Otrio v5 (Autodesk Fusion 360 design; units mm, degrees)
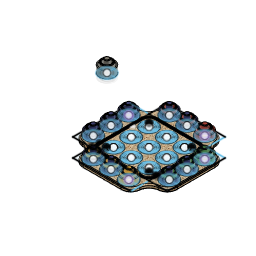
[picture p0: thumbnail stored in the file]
parameter "d19" = 32
parameter "d131" = 37
sketch "Esquisse1" plane through (0, 0, 0) normal (0, 1, 0) x axis (1, 0, 0)
  line L1 (-200.4818, 104.9767) -> (-200.4818, 114.9923)
  line L2 (-199.4818, 104.9731) -> (-199.4818, 114.991)
  circle C1 centre (-200, 100) radius 5
  circle C2 centre (-200, 100) radius 8
  circle C3 centre (-200, 100) radius 11
  circle C4 centre (-200, 100) radius 13
  circle C5 centre (-200, 100) radius 15
  circle C6 centre (-66, 89) radius 11
  circle C7 centre (-66, 89) radius 13
  circle C8 centre (-66, 89) radius 8
  circle C9 centre (-66, 89) radius 15
  circle C10 centre (-66, 89) radius 5
  circle C11 centre (-31, 89) radius 13
  circle C12 centre (-31, 89) radius 8
  circle C13 centre (-31, 89) radius 11
  circle C14 centre (-31, 89) radius 15
  circle C15 centre (-31, 89) radius 5
  circle C16 centre (4, 89) radius 11
  circle C17 centre (4, 89) radius 15
  circle C18 centre (4, 89) radius 13
  circle C19 centre (4, 89) radius 8
  circle C20 centre (4, 89) radius 5
  circle C21 centre (-31, 49) radius 11
  circle C22 centre (-31, 49) radius 5
  circle C23 centre (-31, 49) radius 8
  circle C24 centre (-66, 49) radius 15
  circle C25 centre (4, 49) radius 5
  circle C26 centre (4, 49) radius 13
  circle C27 centre (-31, 49) radius 13
  circle C28 centre (-66, 49) radius 5
  circle C29 centre (4, 49) radius 11
  circle C30 centre (4, 49) radius 15
  circle C31 centre (4, 49) radius 8
  circle C32 centre (-66, 49) radius 11
  circle C33 centre (-31, 49) radius 15
  circle C34 centre (-66, 49) radius 13
  circle C35 centre (-66, 49) radius 8
  circle C36 centre (4, 14) radius 5
  circle C37 centre (4, 14) radius 13
  circle C38 centre (4, 14) radius 8
  circle C39 centre (-31, 14) radius 8
  circle C40 centre (-31, 14) radius 15
  circle C41 centre (-31, 14) radius 11
  circle C42 centre (4, 14) radius 11
  circle C43 centre (-31, 14) radius 13
  circle C44 centre (4, 14) radius 15
  circle C45 centre (-66, 14) radius 15
  circle C46 centre (-31, 14) radius 5
  circle C47 centre (-66, 14) radius 11
  circle C48 centre (-66, 14) radius 5
  circle C49 centre (-66, 14) radius 13
  circle C50 centre (-66, 14) radius 8
  circle C51 centre (-31, -21) radius 15
  circle C52 centre (-31, -21) radius 8
  circle C53 centre (-31, -21) radius 5
  circle C54 centre (4, -21) radius 11
  circle C55 centre (4, -21) radius 8
  circle C56 centre (-66, -21) radius 11
  circle C57 centre (-66, -21) radius 5
  circle C58 centre (-66, -21) radius 13
  circle C59 centre (4, -21) radius 13
  circle C60 centre (-31, -21) radius 13
  circle C61 centre (4, -21) radius 5
  circle C62 centre (-31, -21) radius 11
  circle C63 centre (4, -21) radius 15
  circle C64 centre (-66, -21) radius 8
  circle C65 centre (-66, -21) radius 15
  circle C66 centre (-66, -61) radius 15
  circle C67 centre (-31, -61) radius 5
  circle C68 centre (4, -61) radius 13
  circle C69 centre (-31, -61) radius 15
  circle C70 centre (4, -61) radius 5
  circle C71 centre (4, -61) radius 11
  circle C72 centre (-31, -61) radius 13
  circle C73 centre (-31, -61) radius 11
  circle C74 centre (-31, -61) radius 8
  circle C75 centre (4, -61) radius 15
  circle C76 centre (4, -61) radius 8
  circle C77 centre (-66, -61) radius 13
  circle C78 centre (-66, -61) radius 11
  circle C79 centre (-66, -61) radius 8
  circle C80 centre (-66, -61) radius 5
  circle C81 centre (44, 49) radius 15
  circle C82 centre (44, 49) radius 13
  circle C83 centre (44, 49) radius 11
  circle C84 centre (44, 49) radius 8
  circle C85 centre (44, 49) radius 5
  circle C86 centre (44, 14) radius 15
  circle C87 centre (44, 14) radius 5
  circle C88 centre (44, 14) radius 8
  circle C89 centre (44, 14) radius 13
  circle C90 centre (44, 14) radius 11
  circle C91 centre (44, -21) radius 5
  circle C92 centre (44, -21) radius 11
  circle C93 centre (44, -21) radius 15
  circle C94 centre (44, -21) radius 8
  circle C95 centre (44, -21) radius 13
  circle C96 centre (-106, 49) radius 15
  circle C97 centre (-106, 49) radius 13
  circle C98 centre (-106, 49) radius 11
  circle C99 centre (-106, 49) radius 8
  circle C100 centre (-106, 49) radius 5
  circle C101 centre (-106, 14) radius 8
  circle C102 centre (-106, 14) radius 13
  circle C103 centre (-106, 14) radius 15
  circle C104 centre (-106, 14) radius 5
  circle C105 centre (-106, 14) radius 11
  circle C106 centre (-106, -21) radius 11
  circle C107 centre (-106, -21) radius 13
  circle C108 centre (-106, -21) radius 5
  circle C109 centre (-106, -21) radius 15
  circle C110 centre (-106, -21) radius 8
  point P113 (-200.4818, 114.9923)
  point P114 (-200.4818, 104.9767)
  point P115 (-199.4818, 114.991)
  point P116 (-199.4818, 104.9731)
  concentric C1 C2
  concentric C2 C3
  concentric C2 C4
  concentric C2 C5
  concentric C8 C10
  concentric C6 C8
  concentric C7 C8
  concentric C8 C9
  concentric C12 C15
  concentric C12 C13
  concentric C11 C12
  concentric C12 C14
  concentric C19 C20
  concentric C16 C19
  concentric C18 C19
  concentric C17 C19
  concentric C28 C35
  concentric C32 C35
  concentric C34 C35
  concentric C24 C35
  concentric C22 C23
  concentric C21 C23
  concentric C23 C27
  concentric C23 C33
  concentric C25 C31
  concentric C29 C31
  concentric C26 C31
  concentric C30 C31
  concentric C48 C50
  concentric C47 C50
  concentric C49 C50
  concentric C45 C50
  concentric C39 C46
  concentric C39 C41
  concentric C39 C43
  concentric C39 C40
  concentric C36 C38
  concentric C38 C42
  concentric C37 C38
  concentric C38 C44
  concentric C57 C64
  concentric C56 C64
  concentric C58 C64
  concentric C64 C65
  concentric C52 C53
  concentric C52 C62
  concentric C52 C60
  concentric C51 C52
  concentric C55 C61
  concentric C54 C55
  concentric C55 C59
  concentric C55 C63
  concentric C79 C80
  concentric C78 C79
  concentric C77 C79
  concentric C66 C79
  concentric C67 C74
  concentric C73 C74
  concentric C72 C74
  concentric C69 C74
  concentric C70 C76
  concentric C71 C76
  concentric C68 C76
  concentric C75 C76
  concentric C84 C85
  concentric C83 C84
  concentric C82 C84
  concentric C81 C84
  concentric C87 C88
  concentric C88 C90
  concentric C88 C89
  concentric C86 C88
  concentric C91 C94
  concentric C92 C94
  concentric C94 C95
  concentric C93 C94
  concentric C99 C100
  concentric C98 C99
  concentric C97 C99
  concentric C96 C99
  concentric C101 C104
  concentric C101 C105
  concentric C101 C102
  concentric C101 C103
  concentric C108 C110
  concentric C106 C110
  concentric C107 C110
  concentric C109 C110
  coincident C5 P113
  coincident C1 P114
  vertical L1
  coincident C5 P115
  coincident C1 P116
  parallel L1 L2
  dimension "d3" diameter C1 = 10
  dimension "d4" diameter C2 = 16
  dimension "d5" diameter C3 = 22
  dimension "d6" diameter C4 = 26
  dimension "d7" diameter C5 = 30
  dimension "d24" diameter C10 = 10
  dimension "d25" diameter C8 = 16
  dimension "d26" diameter C6 = 22
  dimension "d27" diameter C7 = 26
  dimension "d28" diameter C9 = 30
  dimension "d29" diameter C15 = 10
  dimension "d30" diameter C12 = 16
  dimension "d31" diameter C13 = 22
  dimension "d32" diameter C11 = 26
  dimension "d33" diameter C14 = 30
  dimension "d34" diameter C20 = 10
  dimension "d35" diameter C19 = 16
  dimension "d36" diameter C16 = 22
  dimension "d37" diameter C18 = 26
  dimension "d38" diameter C17 = 30
  dimension "d39" diameter C28 = 10
  dimension "d40" diameter C35 = 16
  dimension "d41" diameter C32 = 22
  dimension "d42" diameter C34 = 26
  dimension "d43" diameter C24 = 30
  dimension "d44" diameter C22 = 10
  dimension "d45" diameter C23 = 16
  dimension "d46" diameter C21 = 22
  dimension "d47" diameter C27 = 26
  dimension "d48" diameter C33 = 30
  dimension "d49" diameter C25 = 10
  dimension "d50" diameter C31 = 16
  dimension "d51" diameter C29 = 22
  dimension "d52" diameter C26 = 26
  dimension "d53" diameter C30 = 30
  dimension "d54" diameter C48 = 10
  dimension "d55" diameter C50 = 16
  dimension "d56" diameter C47 = 22
  dimension "d57" diameter C49 = 26
  dimension "d58" diameter C45 = 30
  dimension "d59" diameter C46 = 10
  dimension "d60" diameter C39 = 16
  dimension "d61" diameter C41 = 22
  dimension "d62" diameter C43 = 26
  dimension "d63" diameter C40 = 30
  dimension "d64" diameter C36 = 10
  dimension "d65" diameter C38 = 16
  dimension "d66" diameter C42 = 22
  dimension "d67" diameter C37 = 26
  dimension "d68" diameter C44 = 30
  dimension "d69" diameter C57 = 10
  dimension "d70" diameter C64 = 16
  dimension "d71" diameter C56 = 22
  dimension "d72" diameter C58 = 26
  dimension "d73" diameter C65 = 30
  dimension "d74" diameter C53 = 10
  dimension "d75" diameter C52 = 16
  dimension "d76" diameter C62 = 22
  dimension "d77" diameter C60 = 26
  dimension "d78" diameter C51 = 30
  dimension "d79" diameter C61 = 10
  dimension "d80" diameter C55 = 16
  dimension "d81" diameter C54 = 22
  dimension "d82" diameter C59 = 26
  dimension "d83" diameter C63 = 30
  dimension "d84" diameter C80 = 10
  dimension "d85" diameter C79 = 16
  dimension "d86" diameter C78 = 22
  dimension "d87" diameter C77 = 26
  dimension "d88" diameter C66 = 30
  dimension "d89" diameter C67 = 10
  dimension "d90" diameter C74 = 16
  dimension "d91" diameter C73 = 22
  dimension "d92" diameter C72 = 26
  dimension "d93" diameter C69 = 30
  dimension "d94" diameter C70 = 10
  dimension "d95" diameter C76 = 16
  dimension "d96" diameter C71 = 22
  dimension "d97" diameter C68 = 26
  dimension "d98" diameter C75 = 30
  dimension "d99" diameter C85 = 10
  dimension "d100" diameter C84 = 16
  dimension "d101" diameter C83 = 22
  dimension "d102" diameter C82 = 26
  dimension "d103" diameter C81 = 30
  dimension "d104" diameter C87 = 10
  dimension "d105" diameter C88 = 16
  dimension "d106" diameter C90 = 22
  dimension "d107" diameter C89 = 26
  dimension "d108" diameter C86 = 30
  dimension "d109" diameter C91 = 10
  dimension "d110" diameter C94 = 16
  dimension "d111" diameter C92 = 22
  dimension "d112" diameter C95 = 26
  dimension "d113" diameter C93 = 30
  dimension "d114" diameter C100 = 10
  dimension "d115" diameter C99 = 16
  dimension "d116" diameter C98 = 22
  dimension "d117" diameter C97 = 26
  dimension "d118" diameter C96 = 30
  dimension "d119" diameter C104 = 10
  dimension "d120" diameter C101 = 16
  dimension "d121" diameter C105 = 22
  dimension "d122" diameter C102 = 26
  dimension "d123" diameter C103 = 30
  dimension "d124" diameter C108 = 10
  dimension "d125" diameter C110 = 16
  dimension "d126" diameter C106 = 22
  dimension "d127" diameter C107 = 26
  dimension "d128" diameter C109 = 30
  dimension "d173" distance L1 L2 = 1
extrude "Extrusion1" new body sketch "Esquisse1" profile of C1 along normal blind 25 bodies "Petit"
extrude "Extrusion2" new body sketch "Esquisse1" profile of C2 C3 along normal blind 20 bodies "Moyen"
extrude "Extrusion3" new body sketch "Esquisse1" profile of C4 C5 along normal blind 15 bodies "Grand"
sketch "Esquisse2" plane through (0, 0, 0) normal (0, 1, 0) x axis (1, 0, 0)
  line L1 (26, 71) -> (-88, 71)
  line L2 (26, -28) -> (26, 56)
  line L3 (-73, -43) -> (26, -43)
  line L4 (-88, 56) -> (-88, -43)
  line L5 (11, 71) -> (-73, 71)
  line L6 (26, 107) -> (26, 71)
  line L7 (-88, 107) -> (26, 107)
  line L8 (-88, 71) -> (-88, 107)
  line L9 (-124, -43) -> (-88, -43)
  line L10 (-124, 71) -> (-124, -43)
  line L11 (-88, 71) -> (-124, 71)
  line L12 (-88, -28) -> (-88, 71)
  line L13 (62, -43) -> (26, -43)
  line L14 (62, 71) -> (62, -43)
  line L15 (26, 71) -> (62, 71)
  line L16 (26, -43) -> (26, 71)
  line L17 (11, -43) -> (-88, -43)
  line L18 (26, -79) -> (26, -43)
  line L19 (-88, -79) -> (26, -79)
  line L20 (-88, -43) -> (-88, -79)
  line L21 (-86.5, 56) -> (-86.5, -43)
  line L22 (11, 69.5) -> (-73, 69.5)
  line L23 (24.5, -28) -> (24.5, 56)
  line L24 (11, -41.5) -> (-88, -41.5)
  circle C1 centre (4, 89) radius 5
  circle C2 centre (44, 49) radius 5
  circle C3 centre (-106, 49) radius 5
  circle C4 centre (4, -61) radius 5
  arc A1 centre (-73, 56) radius 15 clockwise from (-88, 56) to (-73, 71)
  arc A2 centre (11, 56) radius 15 clockwise from (11, 71) to (26, 56)
  arc A3 centre (-73, -28) radius 15 clockwise from (-73, -43) to (-88, -28)
  arc A4 centre (11, -28) radius 15 clockwise from (26, -28) to (11, -43)
  arc A5 centre (-73, 56) radius 13.5 clockwise from (-86.5, 56) to (-73, 69.5)
  arc A6 centre (11, 56) radius 13.5 clockwise from (11, 69.5) to (24.5, 56)
  arc A7 centre (11, -28) radius 13.5 clockwise from (24.5, -28) to (11, -41.5)
  arc A8 centre (-73, -28) radius 13.5 clockwise from (-73, -41.5) to (-86.5, -28)
  point P2 (-88, 71)
  point P3 (26, 71)
  point P6 (26, 71)
  point P5 (-88, -43)
  point P15 (26, -43)
  point P4 (26, -43)
  point P18 (4, 89)
  point P19 (44, 49)
  point P20 (-106, 49)
  point P21 (4, -61)
  horizontal L1
  vertical L2
  horizontal L3
  vertical L4
  horizontal L5
  vertical L6
  horizontal L7
  vertical L8
  horizontal L9
  vertical L10
  horizontal L11
  vertical L12
  horizontal L13
  vertical L14
  horizontal L15
  vertical L16
  horizontal L17
  vertical L18
  horizontal L19
  vertical L20
  coincident P2 L4
  coincident P2 L5
  tangent L4 A1
  tangent L5 A1
  coincident P3 L2
  coincident P6 L5
  tangent L2 A2
  tangent L5 A2
  equal A1 A2
  coincident P5 L12
  coincident P5 L3
  tangent L12 A3
  tangent L3 A3
  equal A1 A3
  coincident P15 L17
  coincident P4 L2
  tangent L17 A4
  tangent L2 A4
  equal A1 A4
  dimension "d137" distance L5 L7 = 36
  dimension "d138" distance L7 P18 = 18
  dimension "d139" distance L2 L14 = 36 (= "d137")
  dimension "d140" distance L4 L10 = 36 (= "d137")
  dimension "d141" distance L3 L19 = 36 (= "d137")
  dimension "d142" distance L14 P19 = 18 (= "d138")
  dimension "d143" distance L10 P20 = 18 (= "d138")
  dimension "d144" distance L19 P21 = 18 (= "d138")
  dimension "d153" radius A1 = 15
  dimension "d154" = 1.5
  dimension "d155" = -1.5
  dimension "d156" = -1.5
extrude "Extrusion4" new body sketch "Esquisse2" profile of L1 L2 L3 L4 L5 L6 L7 L8 L9 L10 L11 L12 L13 L14 L15 L16 L17 L18 L19 L20 C1 C2 C3 C4 against normal blind 8
extrude "Extrusion5" cut sketch "Esquisse1" profile of C6 C7 C8 C9 C10 C11 C12 C13 C14 C15 C16 C17 C18 C19 C20 C21 C22 C23 C24 C25 C26 C27 C28 C29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 against normal blind 4
fillet "Congé1" radius 1
fillet "Congé2" radius 20
extrude "Extrusion6" cut sketch "Esquisse2" profile of L1 L2 L3 L4 L5 L12 L16 L17 A1 A2 A3 A4 L21 L23 A5 L22 A6 L24 A7 A8 against normal blind 1
fillet "Congé3" radius 2
fillet "Congé4" radius 2.5
fillet "Congé5" radius 1
fillet "Congé6" radius 1.75
fillet "Congé7" radius 2.5
copy_paste_bodies "Copier/Coller des corps1"
move "Déplacer1"
rectangular_pattern "Réseau R" uSpaceDistance 70 vSpaceDistance 0 bodies "Moyen (1) (1)", "Moyen (1) (2)", "Petit (1) (1)", "Petit (1) (2)", "Grand (1) (1)", "Grand (1) (2)"
copy_paste_bodies "Copier/Coller des corps2"
move "Déplacer2"
copy_paste_bodies "Copier/Coller des corps3"
move "Déplacer3"
extrude "Extrusion8" add sketch "Esquisse1" profile of C1 C2 C3 C4 C5 L1 L2 along normal blind 1 bodies "Petit", "Grand"
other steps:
base_feature "Fonction de base1" bodies "Moyen", "Petit (1)", "Moyen (1)", "Grand (1)", "Moyen (3)", "Petit", "Grand"
base_feature "Fonction de base2" bodies "Petit (1)", "Moyen (1) (2)", "Moyen (1)", "Moyen (1) (1)", "Grand (1)", "Petit (1) (2)", "Petit (1) (3)", "Moyen (1) (2) (1)"
base_feature "Fonction de base3" bodies "Petit (1) (3)", "Moyen (1) (2) (1)", "Moyen (1) (3)", "Moyen (1) (1) (1)", "Grand (1) (3)", "Petit (1) (2) (1)", "Petit (1) (3) (1)", "Moyen (1) (2) (1) (1)"
named bodies: "Petit", "Moyen", "Grand", "Plateau", "Petit (1)", "Moyen (1)", "Grand (1)", "Moyen (1) (1)", "Moyen (1) (2)", "Petit (1) (2)", "Petit (1) (3)", "Moyen (1) (2) (1)", "Moyen (1) (3)", "Moyen (1) (1) (1)", "Grand (1) (3)", "Petit (1) (2) (1)", "Petit (1) (3) (1)", "Moyen (1) (2) (1) (1)", "Moyen (1) (3) (1)", "Grand (1) (2) (2)", "Grand (1) (3) (1)", "Moyen (1) (1) (1) (1)", "Petit (1) (3) (1) (1)", "Moyen (1) (2) (1) (1) (1)", "Moyen (1) (3) (1) (1)", "Grand (1) (3) (1) (1)", "Moyen (1) (1) (1) (1) (1)", "Moyen (3)", "Petit (1) (1)", "Grand (1) (1)", "Grand (1) (2)", "Petit (1) (2) (2)", "Grand (1) (1) (1)", "Petit (1) (1) (1)", "Grand (1) (2) (1)", "Petit (1) (2) (3)", "Petit (1) (2) (2) (1)", "Petit (1) (1) (1) (1)", "Grand (1) (2) (3)", "Grand (1) (1) (1) (1)", "Grand (1) (2) (1) (1)", "Petit (1) (1) (1) (1) (1)", "Grand (1) (1) (1) (1) (1)"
